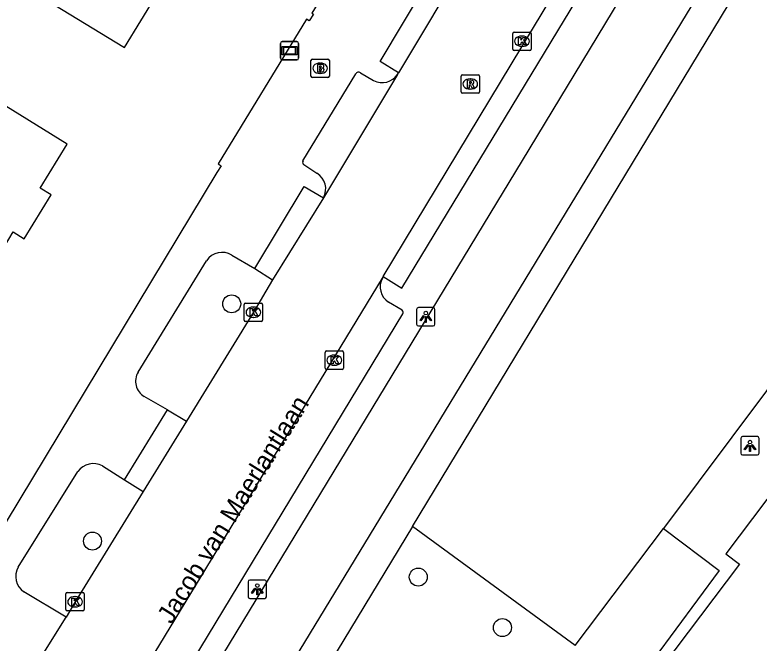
# Model space of a CAD drawing. Extents: x 160356 to 161355, y 381727 to 382845.
# Drawn here: x 161044.96 to 161085.41, y 382137.49 to 382171.61 of the extents above; entities that cross this region are included whole.
import ezdxf

# ---------------------------------------------------------------- set-up
doc = ezdxf.new("R2010")
doc.units = 0
for name, color, linetype in [('IMGEO_Boom', 7, 'Continuous'), ('IMGEO_Brandkraan', 7, 'Continuous'), ('IMGEO_Fietspad_gesloten', 7, 'Continuous'), ('IMGEO_Kolk', 7, 'Continuous'), ('IMGEO_Lichtpunt', 7, 'Continuous'), ('IMGEO_Openbare_ruimte_label', 7, 'Continuous'), ('IMGEO_Pand', 7, 'Continuous'), ('IMGEO_Parkeervlak_open', 7, 'Continuous'), ('IMGEO_Rijbaan_lokaal_open', 7, 'Continuous'), ('IMGEO_Rioolput', 7, 'Continuous'), ('IMGEO_Verklikker', 7, 'Continuous'), ('IMGEO_Voetpad_open', 7, 'Continuous')]:
    doc.layers.add(name, color=color, linetype=linetype)

msp = doc.modelspace()

# ---------------------------------------------------------------- linework, layer by layer
at = {"layer": 'IMGEO_Boom'}
for centre in [(161056.745, 382155.914), (161049.178, 382143.025), (161066.888, 382141.073), (161071.46, 382138.327)]:
    msp.add_circle(centre, 0.489, dxfattribs=at)
at = {"layer": 'IMGEO_Brandkraan'}
for p, q in [((161061.053, 382168.285), (161061.053, 382169.137)), ((161061.128, 382169.211), (161061.98, 382169.211)), ((161062.054, 382169.137), (161062.054, 382168.285)), ((161061.541, 382168.991), (161061.566, 382168.991)), ((161061.564, 382168.431), (161061.539, 382168.431)), ((161061.98, 382168.211), (161061.128, 382168.211))]:
    msp.add_line(p, q, dxfattribs=at)
for points in [[(161061.053, 382168.285), (161061.053, 382169.137)], [(161061.128, 382169.211), (161061.98, 382169.211)], [(161062.054, 382169.137), (161062.054, 382168.285)], [(161061.401, 382168.911), (161061.401, 382168.511), (161061.614, 382168.511)], [(161061.632, 382168.911), (161061.401, 382168.911)], [(161061.58, 382168.83), (161061.526, 382168.83), (161061.526, 382168.754)], [(161061.526, 382168.754), (161061.579, 382168.754)], [(161061.588, 382168.678), (161061.526, 382168.678), (161061.526, 382168.597)], [(161061.526, 382168.597), (161061.588, 382168.597)], [(161061.98, 382168.211), (161061.128, 382168.211)]]:
    msp.add_lwpolyline(points, dxfattribs=at)
for centre, radius, start, end in [((161061.13, 382169.135), 0.0765, 91.552, 178.448), ((161061.13, 382169.135), 0.0765, 91.552, 178.448), ((161061.978, 382169.135), 0.0765, 1.552, 88.448), ((161061.978, 382169.135), 0.0765, 1.552, 88.448), ((161061.581, 382168.792), 0.0379, 267.8285, 90.9355), ((161061.589, 382168.637), 0.0404, 269.8759, 90.5077), ((161061.636, 382168.766), 0.145, 59.4692, 91.5367), ((161061.661, 382168.813), 0.0922, 285.5137, 58.1501), ((161061.666, 382168.621), 0.105, 301.3115, 78.989), ((161061.13, 382168.287), 0.0765, 181.552, 268.448), ((161061.13, 382168.287), 0.0765, 181.552, 268.448), ((161061.62, 382168.762), 0.251, 268.6676, 293.5347), ((161061.978, 382168.287), 0.0765, 271.552, 358.448), ((161061.978, 382168.287), 0.0765, 271.552, 358.448)]:
    msp.add_arc(centre, radius, start, end, dxfattribs=at)
for centre, major_axis, ratio, start_param, end_param in [((161061.54, 382168.711), (-0.387, 0.002), 0.722429, 4.712389, 7.853982), ((161061.565, 382168.711), (-0.39, 0.002), 0.717154, 1.570796, 4.712389)]:
    msp.add_ellipse(centre, major_axis=major_axis, ratio=ratio, start_param=start_param, end_param=end_param, dxfattribs=at)
at = {"layer": 'IMGEO_Fietspad_gesloten'}
for points in [[(161036.885, 382104.942), (161037.001, 382105.126), (161044.262, 382117.085), (161072.545, 382163.708), (161094.564, 382200.063)], [(161040.022, 382103.393), (161049.862, 382119.664), (161056.078, 382129.917), (161089.928, 382185.548)]]:
    msp.add_lwpolyline(points, dxfattribs=at)
at = {"layer": 'IMGEO_Kolk'}
for p, q in [((161072.098, 382170.679), (161072.95, 382170.679)), ((161072.023, 382169.753), (161072.023, 382170.605)), ((161072.511, 382170.459), (161072.536, 382170.459)), ((161073.024, 382170.605), (161073.024, 382169.753)), ((161072.534, 382169.899), (161072.509, 382169.899)), ((161072.95, 382169.679), (161072.098, 382169.679)), ((161057.425, 382155.033), (161057.425, 382155.885)), ((161057.5, 382155.959), (161058.352, 382155.959)), ((161057.913, 382155.739), (161057.938, 382155.739)), ((161058.426, 382155.885), (161058.426, 382155.033)), ((161058.352, 382154.959), (161057.5, 382154.959)), ((161057.936, 382155.179), (161057.911, 382155.179)), ((161061.825, 382152.428), (161061.825, 382153.28)), ((161061.9, 382153.354), (161062.752, 382153.354)), ((161062.826, 382153.28), (161062.826, 382152.428)), ((161062.313, 382153.134), (161062.338, 382153.134)), ((161062.336, 382152.574), (161062.311, 382152.574)), ((161062.752, 382152.354), (161061.9, 382152.354)), ((161047.732, 382139.305), (161047.732, 382140.157)), ((161047.807, 382140.231), (161048.659, 382140.231)), ((161048.22, 382140.011), (161048.245, 382140.011)), ((161048.733, 382140.157), (161048.733, 382139.305)), ((161048.659, 382139.231), (161047.807, 382139.231)), ((161048.243, 382139.451), (161048.218, 382139.451))]:
    msp.add_line(p, q, dxfattribs=at)
for points in [[(161072.098, 382170.679), (161072.95, 382170.679)], [(161072.023, 382169.753), (161072.023, 382170.605)], [(161072.344, 382170.379), (161072.467, 382170.379), (161072.467, 382170.228), (161072.597, 382170.379), (161072.761, 382170.379), (161072.615, 382170.228), (161072.768, 382169.979), (161072.616, 382169.979), (161072.531, 382170.143), (161072.467, 382170.076), (161072.467, 382169.979), (161072.344, 382169.979), (161072.344, 382170.379)], [(161073.024, 382170.605), (161073.024, 382169.753)], [(161072.95, 382169.679), (161072.098, 382169.679)], [(161057.425, 382155.033), (161057.425, 382155.885)], [(161057.5, 382155.959), (161058.352, 382155.959)], [(161058.426, 382155.885), (161058.426, 382155.033)], [(161057.746, 382155.659), (161057.869, 382155.659), (161057.869, 382155.508), (161057.999, 382155.659), (161058.163, 382155.659), (161058.017, 382155.508), (161058.17, 382155.259), (161058.018, 382155.259), (161057.933, 382155.423), (161057.869, 382155.356), (161057.869, 382155.259), (161057.746, 382155.259), (161057.746, 382155.659)], [(161058.352, 382154.959), (161057.5, 382154.959)], [(161061.825, 382152.428), (161061.825, 382153.28)], [(161061.9, 382153.354), (161062.752, 382153.354)], [(161062.826, 382153.28), (161062.826, 382152.428)], [(161062.146, 382153.054), (161062.269, 382153.054), (161062.269, 382152.903), (161062.399, 382153.054), (161062.563, 382153.054), (161062.417, 382152.903), (161062.57, 382152.654), (161062.418, 382152.654), (161062.333, 382152.818), (161062.269, 382152.751), (161062.269, 382152.654), (161062.146, 382152.654), (161062.146, 382153.054)], [(161062.752, 382152.354), (161061.9, 382152.354)], [(161047.732, 382139.305), (161047.732, 382140.157)], [(161047.807, 382140.231), (161048.659, 382140.231)], [(161048.053, 382139.931), (161048.176, 382139.931), (161048.176, 382139.78), (161048.306, 382139.931), (161048.47, 382139.931), (161048.324, 382139.78), (161048.477, 382139.531), (161048.325, 382139.531), (161048.24, 382139.695), (161048.176, 382139.628), (161048.176, 382139.531), (161048.053, 382139.531), (161048.053, 382139.931)], [(161048.733, 382140.157), (161048.733, 382139.305)], [(161048.659, 382139.231), (161047.807, 382139.231)]]:
    msp.add_lwpolyline(points, dxfattribs=at)
for centre, start, end in [((161072.1, 382170.603), 91.552, 178.448), ((161072.1, 382170.603), 91.552, 178.448), ((161072.948, 382170.603), 1.552, 88.448), ((161072.948, 382170.603), 1.552, 88.448), ((161072.1, 382169.755), 181.552, 268.448), ((161072.1, 382169.755), 181.552, 268.448), ((161072.948, 382169.755), 271.552, 358.448), ((161072.948, 382169.755), 271.552, 358.448), ((161057.502, 382155.883), 91.552, 178.448), ((161057.502, 382155.883), 91.552, 178.448), ((161058.35, 382155.883), 1.552, 88.448), ((161058.35, 382155.883), 1.552, 88.448), ((161057.502, 382155.035), 181.552, 268.448), ((161057.502, 382155.035), 181.552, 268.448), ((161058.35, 382155.035), 271.552, 358.448), ((161058.35, 382155.035), 271.552, 358.448), ((161061.902, 382153.278), 91.552, 178.448), ((161061.902, 382153.278), 91.552, 178.448), ((161062.75, 382153.278), 1.552, 88.448), ((161062.75, 382153.278), 1.552, 88.448), ((161061.902, 382152.43), 181.552, 268.448), ((161061.902, 382152.43), 181.552, 268.448), ((161062.75, 382152.43), 271.552, 358.448), ((161062.75, 382152.43), 271.552, 358.448), ((161047.809, 382140.155), 91.552, 178.448), ((161047.809, 382140.155), 91.552, 178.448), ((161048.657, 382140.155), 1.552, 88.448), ((161048.657, 382140.155), 1.552, 88.448), ((161047.809, 382139.307), 181.552, 268.448), ((161047.809, 382139.307), 181.552, 268.448), ((161048.657, 382139.307), 271.552, 358.448), ((161048.657, 382139.307), 271.552, 358.448)]:
    msp.add_arc(centre, 0.0765, start, end, dxfattribs=at)
for centre, major_axis, ratio, start_param, end_param in [((161072.51, 382170.179), (-0.387, 0.002), 0.722429, 4.712389, 7.853982), ((161072.535, 382170.179), (-0.39, 0.002), 0.717154, 1.570796, 4.712389), ((161057.912, 382155.459), (-0.387, 0.002), 0.722429, 4.712389, 7.853982), ((161057.937, 382155.459), (-0.39, 0.002), 0.717154, 1.570796, 4.712389), ((161062.312, 382152.854), (-0.387, 0.002), 0.722429, 4.712389, 7.853982), ((161062.337, 382152.854), (-0.39, 0.002), 0.717154, 1.570796, 4.712389), ((161048.219, 382139.731), (-0.387, 0.002), 0.722429, 4.712389, 7.853982), ((161048.244, 382139.731), (-0.39, 0.002), 0.717154, 1.570796, 4.712389)]:
    msp.add_ellipse(centre, major_axis=major_axis, ratio=ratio, start_param=start_param, end_param=end_param, dxfattribs=at)
at = {"layer": 'IMGEO_Lichtpunt'}
for p, q in [((161067.701, 382155.708), (161066.893, 382155.708)), ((161067.701, 382155.708), (161066.893, 382155.708)), ((161066.799, 382155.613), (161066.799, 382154.806)), ((161066.799, 382155.613), (161066.799, 382154.806)), ((161067.795, 382154.806), (161067.795, 382155.613)), ((161067.795, 382154.806), (161067.795, 382155.613)), ((161066.893, 382154.712), (161067.701, 382154.712)), ((161066.893, 382154.712), (161067.701, 382154.712)), ((161084.418, 382148.606), (161084.418, 382147.799)), ((161084.418, 382148.606), (161084.418, 382147.799)), ((161085.32, 382148.701), (161084.512, 382148.701)), ((161085.32, 382148.701), (161084.512, 382148.701)), ((161085.414, 382147.799), (161085.414, 382148.606)), ((161085.414, 382147.799), (161085.414, 382148.606)), ((161084.512, 382147.705), (161085.32, 382147.705)), ((161084.512, 382147.705), (161085.32, 382147.705)), ((161057.638, 382140.811), (161057.638, 382140.004)), ((161057.638, 382140.811), (161057.638, 382140.004)), ((161058.54, 382140.906), (161057.732, 382140.906)), ((161058.54, 382140.906), (161057.732, 382140.906)), ((161058.634, 382140.004), (161058.634, 382140.811)), ((161058.634, 382140.004), (161058.634, 382140.811)), ((161057.732, 382139.91), (161058.54, 382139.91)), ((161057.732, 382139.91), (161058.54, 382139.91))]:
    msp.add_line(p, q, dxfattribs=at)
for points in [[(161067.173, 382155.277), (161067.212, 382155.249), (161067.024, 382154.987), (161066.986, 382155.014), (161067.173, 382155.277)], [(161067.275, 382155.229), (161067.322, 382155.229), (161067.322, 382154.907), (161067.275, 382154.907), (161067.275, 382155.229)], [(161067.385, 382155.249), (161067.423, 382155.276), (161067.61, 382155.014), (161067.571, 382154.986), (161067.385, 382155.249)], [(161084.792, 382148.27), (161084.831, 382148.242), (161084.643, 382147.98), (161084.605, 382148.007), (161084.792, 382148.27)], [(161084.894, 382148.222), (161084.941, 382148.222), (161084.941, 382147.9), (161084.894, 382147.9), (161084.894, 382148.222)], [(161085.004, 382148.242), (161085.042, 382148.269), (161085.229, 382148.007), (161085.19, 382147.979), (161085.004, 382148.242)], [(161058.012, 382140.475), (161058.051, 382140.447), (161057.863, 382140.185), (161057.825, 382140.212), (161058.012, 382140.475)], [(161058.114, 382140.427), (161058.161, 382140.427), (161058.161, 382140.105), (161058.114, 382140.105), (161058.114, 382140.427)], [(161058.224, 382140.447), (161058.262, 382140.474), (161058.449, 382140.212), (161058.41, 382140.184), (161058.224, 382140.447)]]:
    msp.add_lwpolyline(points, dxfattribs=at)
for centre in [(161067.298, 382155.411), (161084.917, 382148.404), (161058.137, 382140.609)]:
    msp.add_circle(centre, 0.0994, dxfattribs=at)
for centre, start, end in [((161066.893, 382155.613), 90, 180), ((161066.893, 382155.613), 90, 180), ((161067.701, 382155.613), 0, 90), ((161067.701, 382155.613), 0, 90), ((161066.893, 382154.806), 180, 270), ((161066.893, 382154.806), 180, 270), ((161067.701, 382154.806), 270, 0), ((161067.701, 382154.806), 270, 360), ((161084.512, 382148.606), 90, 180), ((161084.512, 382148.606), 90, 180), ((161085.32, 382148.606), 0, 90), ((161085.32, 382148.606), 0, 90), ((161084.512, 382147.799), 180, 270), ((161084.512, 382147.799), 180, 270), ((161085.32, 382147.799), 270, 0), ((161085.32, 382147.799), 270, 360), ((161057.732, 382140.811), 90, 180), ((161057.732, 382140.811), 90, 180), ((161058.54, 382140.811), 0, 90), ((161058.54, 382140.811), 0, 90), ((161057.732, 382140.004), 180, 270), ((161057.732, 382140.004), 180, 270), ((161058.54, 382140.004), 270, 0), ((161058.54, 382140.004), 270, 360)]:
    msp.add_arc(centre, 0.0946, start, end, dxfattribs=at)
at = {"layer": 'IMGEO_Pand'}
for points in [[(161036.389, 382190.194), (161034.602, 382187.229), (161043.01, 382182.163), (161041.602, 382179.861), (161043.122, 382178.931), (161041.203, 382175.8), (161043.493, 382174.397), (161046.658, 382172.454), (161050.923, 382169.844), (161054.476, 382175.652), (161050.282, 382178.218), (161047.507, 382179.915), (161049.047, 382182.433), (161043.381, 382185.98)], [(161040.195, 382161.044), (161044.142, 382158.625), (161044.874, 382159.819), (161045.47, 382159.453), (161046.934, 382161.84), (161046.337, 382162.206), (161047.801, 382164.594), (161043.538, 382167.207), (161039.093, 382169.932), (161037.389, 382170.98), (161035.294, 382167.572), (161036.998, 382166.525), (161035.426, 382163.968), (161035.916, 382163.667), (161035.161, 382162.436), (161039.44, 382159.813), (161040.195, 382161.044)], [(161110.736, 382164.311), (161110.433, 382164.541), (161110.972, 382165.239), (161105.316, 382169.518), (161099.802, 382162.195), (161099.037, 382162.772), (161083.609, 382142.34), (161084.351, 382141.78), (161079.433, 382135.265), (161079.013, 382134.714)]]:
    msp.add_lwpolyline(points, dxfattribs=at)
at = {"layer": 'IMGEO_Parkeervlak_open'}
for points in [[(161066.003, 382155.562), (161065.275, 382156.011)], [(161050.17, 382129.175), (161066.053, 382155.37)]]:
    msp.add_lwpolyline(points, dxfattribs=at)
for centre, radius, start, end in [((161065.799, 382156.842), 0.983, 151.3121, 237.772), ((161065.914, 382155.436), 0.154, 334.4145, 54.7786)]:
    msp.add_arc(centre, radius, start, end, dxfattribs=at)
at = {"layer": 'IMGEO_Rijbaan_lokaal_open'}
for points in [[(161069.576, 382174.759), (161065.819, 382168.471)], [(161064.984, 382157.392), (161074.844, 382173.726)], [(161065.759, 382168.371), (161061.736, 382161.678)], [(161065.759, 382168.371), (161065.819, 382168.471)], [(161061.736, 382161.678), (161058.971, 382157.211)], [(161064.937, 382157.314), (161064.984, 382157.392)], [(161048.337, 382130.017), (161064.937, 382157.314)], [(161058.971, 382157.211), (161057.926, 382155.459), (161054.283, 382149.548)], [(161054.283, 382149.548), (161051.931, 382145.72)], [(161051.931, 382145.72), (161048.233, 382139.731), (161047.741, 382138.893)], [(161045.726, 382135.661), (161047.741, 382138.893)]]:
    msp.add_lwpolyline(points, dxfattribs=at)
at = {"layer": 'IMGEO_Rioolput'}
for p, q in [((161069.213, 382167.43), (161069.213, 382168.282)), ((161069.288, 382168.356), (161070.14, 382168.356)), ((161070.214, 382168.282), (161070.214, 382167.43)), ((161069.701, 382168.136), (161069.726, 382168.136)), ((161069.724, 382167.576), (161069.699, 382167.576)), ((161070.14, 382167.356), (161069.288, 382167.356))]:
    msp.add_line(p, q, dxfattribs=at)
for points in [[(161069.213, 382167.43), (161069.213, 382168.282)], [(161069.288, 382168.356), (161070.14, 382168.356)], [(161070.214, 382168.282), (161070.214, 382167.43)], [(161069.802, 382168.054), (161069.55, 382168.056), (161069.55, 382167.656)], [(161069.728, 382167.975), (161069.674, 382167.975), (161069.674, 382167.894)], [(161069.674, 382167.894), (161069.726, 382167.894)], [(161069.55, 382167.656), (161069.674, 382167.656), (161069.674, 382167.818), (161069.685, 382167.818)], [(161069.732, 382167.789), (161069.803, 382167.656), (161069.943, 382167.656), (161069.878, 382167.782)], [(161070.14, 382167.356), (161069.288, 382167.356)]]:
    msp.add_lwpolyline(points, dxfattribs=at)
for centre, radius, start, end in [((161069.29, 382168.28), 0.0765, 91.552, 178.448), ((161069.29, 382168.28), 0.0765, 91.552, 178.448), ((161070.138, 382168.28), 0.0765, 1.552, 88.448), ((161070.138, 382168.28), 0.0765, 1.552, 88.448), ((161069.71, 382168.083), 0.19, 274.7715, 282.9687), ((161069.734, 382167.879), 0.0964, 77.0061, 93.1865), ((161069.748, 382167.936), 0.0378, 276.6634, 79.6772), ((161069.801, 382167.944), 0.109, 350.3612, 89.416), ((161069.799, 382167.944), 0.112, 277.5842, 350.9817), ((161069.684, 382167.765), 0.0533, 26.0293, 88.6989), ((161069.783, 382167.729), 0.108, 29.5134, 73.7905), ((161069.29, 382167.432), 0.0765, 181.552, 268.448), ((161069.29, 382167.432), 0.0765, 181.552, 268.448), ((161070.138, 382167.432), 0.0765, 271.552, 358.448), ((161070.138, 382167.432), 0.0765, 271.552, 358.448)]:
    msp.add_arc(centre, radius, start, end, dxfattribs=at)
for centre, major_axis, ratio, start_param, end_param in [((161069.7, 382167.856), (-0.387, 0.002), 0.722429, 4.712389, 7.853982), ((161069.725, 382167.856), (-0.39, 0.002), 0.717154, 1.570796, 4.712389)]:
    msp.add_ellipse(centre, major_axis=major_axis, ratio=ratio, start_param=start_param, end_param=end_param, dxfattribs=at)
at = {"layer": 'IMGEO_Verklikker'}
for p, q in [((161059.394, 382169.263), (161059.394, 382170.063)), ((161059.394, 382170.063), (161059.394, 382169.263)), ((161059.494, 382170.163), (161060.284, 382170.163)), ((161060.284, 382170.163), (161059.494, 382170.163)), ((161060.384, 382170.063), (161060.384, 382169.263)), ((161060.384, 382169.263), (161060.384, 382170.063)), ((161060.284, 382169.163), (161059.494, 382169.163)), ((161059.494, 382169.163), (161060.284, 382169.163))]:
    msp.add_line(p, q, dxfattribs=at)
for points in [[(161059.495, 382169.895), (161060.283, 382169.895), (161060.283, 382169.431), (161059.495, 382169.431), (161059.495, 382169.895)], [(161059.56, 382169.83), (161059.56, 382169.496), (161060.218, 382169.496), (161060.218, 382169.83), (161059.56, 382169.83)]]:
    msp.add_lwpolyline(points, dxfattribs=at)
for centre, start, end in [((161059.494, 382170.063), 90, 180), ((161059.494, 382170.063), 90, 180), ((161060.284, 382170.063), 0, 90), ((161060.284, 382170.063), 360, 90), ((161059.494, 382169.263), 180, 270), ((161059.494, 382169.263), 180, 270), ((161060.284, 382169.263), 270, 0), ((161060.284, 382169.263), 270, 0)]:
    msp.add_arc(centre, 0.1, start, end, dxfattribs=at)
at = {"layer": 'IMGEO_Voetpad_open'}
for points in [[(161077.695, 382198.842), (161070.729, 382187.418), (161064.28, 382176.744), (161064.17, 382176.808), (161062.761, 382174.449), (161062.847, 382174.398), (161062.457, 382173.745), (161062.375, 382173.794), (161061.094, 382171.7), (161061.183, 382171.645), (161060.957, 382171.279), (161060.816, 382171.371), (161056.01, 382163.511), (161056.164, 382163.417), (161055.939, 382163.048), (161043.037, 382141.705), (161038.497, 382134.216), (161035.847, 382129.872), (161033.249, 382125.808), (161031.264, 382122.813), (161028.977, 382119.491), (161027.146, 382116.964), (161024.567, 382113.497), (161022.432, 382110.606)], [(161066.578, 382143.827), (161091.332, 382184.687)], [(161065.819, 382168.471), (161064.808, 382169.081), (161068.558, 382175.362)], [(161064.984, 382157.392), (161065.988, 382156.772), (161075.873, 382173.06), (161074.844, 382173.726)], [(161060.621, 382163.686), (161063.485, 382168.401)], [(161063.747, 382168.47), (161064.462, 382168.052)], [(161096.957, 382166.077), (161080.216, 382143.711)], [(161061.377, 382163.003), (161060.661, 382163.456)], [(161058.012, 382157.835), (161060.683, 382162.296), (161061.736, 382161.678)], [(161056.761, 382158.558), (161058.012, 382157.835)], [(161051.661, 382152.205), (161055.369, 382158.251)], [(161058.012, 382157.835), (161058.971, 382157.211)], [(161053.252, 382150.15), (161051.995, 382150.878)], [(161050.919, 382146.361), (161053.252, 382150.15)], [(161053.252, 382150.15), (161054.283, 382149.548)], [(161045.146, 382141.616), (161048.382, 382146.811)], [(161049.728, 382147.112), (161050.919, 382146.361)], [(161050.919, 382146.361), (161051.931, 382145.72)], [(161066.578, 382143.827), (161057.61, 382129.027), (161051.511, 382118.968), (161047.156, 382111.778), (161045.108, 382108.396), (161043.227, 382105.29), (161042.601, 382104.257), (161041.012, 382101.633)], [(161075.411, 382137.347), (161066.578, 382143.827)], [(161075.411, 382137.347), (161080.216, 382143.711)], [(161080.216, 382143.711), (161083.247, 382141.432), (161078.535, 382135.055)], [(161047.741, 382138.893), (161045.443, 382140.274)]]:
    msp.add_lwpolyline(points, dxfattribs=at)
for centre, radius, start, end in [((161063.65, 382168.305), 0.191, 59.5773, 149.9314), ((161064.932, 382168.936), 1.001, 241.9827, 325.6528), ((161060.798, 382163.598), 0.197, 153.5607, 226.1709), ((161060.863, 382162.153), 0.994, 331.4613, 58.8586), ((161056.226, 382157.675), 1.032, 58.773, 146.1015), ((161052.478, 382151.705), 0.958, 148.5331, 239.7222), ((161049.232, 382146.168), 1.066, 62.3072, 142.9036), ((161045.998, 382141.101), 0.995, 148.8138, 236.1443)]:
    msp.add_arc(centre, radius, start, end, dxfattribs=at)

# ---------------------------------------------------------------- texts
at = {"layer": 'IMGEO_Openbare_ruimte_label'}
msp.add_text('Jacob van Maerlantlaan', height=1, rotation=58.0735, dxfattribs=at).set_placement((161053.482, 382138.466))

doc.saveas('drawing.dxf')
